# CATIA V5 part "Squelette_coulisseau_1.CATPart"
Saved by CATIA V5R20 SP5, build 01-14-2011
Part number: Squelette_coulisseau_1
Publications: "Plan xy", "Plan yz", "Plan zx", "Point.1", "Point.2", "Point.3", "Point.4", "Droite.1", "Droite.2", "Droite.3", "Droite.4", "Point.5", "Droite.5", "Longueur_coulisseau_1", "Largeur_coulisseau_1"
Bounding box of the stored display mesh (mm): x 0 to 14, y 0 to 10, z 0 to 20
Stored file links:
  C:\Users\MARLENE\Documents\IFMA\S3\IAO\Copie de CAO\Squelette_coulisseau_1.CATPart
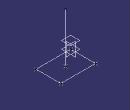
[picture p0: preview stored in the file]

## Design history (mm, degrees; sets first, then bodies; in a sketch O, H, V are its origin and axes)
Parameters
  Longueur_coulisseau_1 = 14 mm
  Largeur_coulisseau_1 = 10 mm
Set1
  Point1: (0, 0, 0)
  Point2: (14 {= Longueur_coulisseau_1}, 0, 0)
  Point3: (14 {= Longueur_coulisseau_1}, 10 {= Largeur_coulisseau_1}, 0)
  Point4: (0, 10 {= Largeur_coulisseau_1}, 0)
  Line1: type PtPt, FirstPoint Point1, SecondPoint Point4
  Line2: type PtPt, FirstPoint Point4, SecondPoint Point3
  Line3: type PtPt, FirstPoint Point1, SecondPoint Point2
  Line4: type PtPt, FirstPoint Point2, SecondPoint Point3
  Point5: (7 {= Longueur_coulisseau_1 /2}, 5 {= Largeur_coulisseau_1 /2}, 0)
  Line5: type PtDir, RefPoint Point5, Direction xy-plane, Start 0, End 20
  Plane1: type Offset, RefPlane xy-plane, Offset 3
Body1 (main body)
